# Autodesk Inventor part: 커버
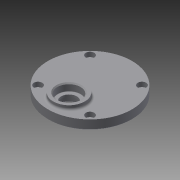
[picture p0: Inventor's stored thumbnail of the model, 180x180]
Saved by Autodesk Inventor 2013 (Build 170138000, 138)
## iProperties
Created: 2015-07
Part Number: 커버
Material: 일반
Document SubType Name: Modeling
Designer: user
Density: 1 g/cm^3
Author: user
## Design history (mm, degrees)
sketch "스케치1"
  geometry: C1 r 40 at (0, 0); 1 further point
  constraints: 1 centre point, 1 coincident
  dimensions: "d0" = 80 diameter of C1
extrude "돌출1" new body sketch "스케치1" distance "d1" = 9; taper "d2" = 0 deg
sketch "스케치2"
  geometry: C1 r 40 at (0, 0) reference; C2 r 15 at (0, -20)
  constraints: 1 centre point, 1 vertical alignment
  dimensions: "d3" = 30 diameter of C2; "d4" = 20 distance of C1.centre C2.centre
extrude "돌출2" join sketch "스케치2" distance "d5" = 4; taper "d6" = 0 deg
sketch "스케치3"
  geometry: C1 r 15 at (0, 0) reference; C2 r 11 at (0, 0); 1 further point
  constraints: 1 centre point, 1 coincident
  dimensions: "d7" = 22 diameter of C2
extrude "돌출3" cut sketch "스케치3" distance "d8" = 7; taper "d9" = 0 deg
sketch "스케치4"
  geometry: C1 r 11 at (0, 0) reference; C2 r 7.5 at (0, 0); 1 further point
  constraints: 1 centre point, 1 coincident
  dimensions: "d10" = 15 diameter of C2
extrude "돌출4" cut sketch "스케치4" distance "d12" = 2; taper "d13" = 0 deg
sketch "스케치5"
  geometry: C1 r 7.5 at (0, 0) reference; C2 r 11 at (0, 0); 1 further point
  constraints: 1 centre point, 1 coincident
  dimensions: "d14" = 22 diameter of C2
extrude "돌출5" cut sketch "스케치5" distance "d15" = 7; taper "d16" = 0 deg
sketch "스케치6"
  geometry: C1 r 11 at (0, -20) reference; C2 r 40 at (0, 0) reference; C3 r 14 at (0, -20); C4 r 14 at (0, 11)
  constraints: 2 centre point, 1 coincident, 1 vertical alignment
  dimensions: "d17" = 28 diameter of C3; "d18" = 28 diameter of C4; "d19" = 11 distance of C2.centre C4.centre
extrude "돌출6" join sketch "스케치6" distance "d20" = 3; taper "d21" = 0 deg
sketch "스케치7"
  geometry: C1 r 14 at (0, 0) reference; C2 r 11 at (0, 0); 1 further point
  constraints: 1 centre point, 1 coincident
  dimensions: "d22" = 22 diameter of C2
extrude "돌출7" cut sketch "스케치7" distance "d23" = 7; taper "d24" = 0 deg
sketch "스케치8"
  geometry: C1 r 9 at (0, 0); 2 further points
  constraints: 1 centre point, 1 coincident, 1 vertical alignment
  dimensions: "d25" = 18 diameter of C1
extrude "돌출8" cut sketch "스케치8" distance "d26" = 1; taper "d27" = 0 deg
sketch "스케치9"
  geometry: L1 (0, 0)-(16.369, 0); L2 (24.749, 24.749)-(-24.749, -24.749); L3 (-24.749, 24.749)-(24.749, -24.749); C1 r 40 at (0, 0) reference; C2 r 2.25 at (-24.749, 24.749); A1 r 35 centre (0, 0) between (24.749, 24.749) and (-24.749, -24.749)
  constraints: 6 end point, 4 point on circle, 2 centre point, 2 coincident, 2 midpoint, 1 horizontal
  dimensions: "d28" = 70 diameter of A1; "d29" = 45 deg angle of L1 L2; "d31" = 90 deg angle of L3 L2; "d33" = 4.5 diameter of C2
extrude "돌출9" cut sketch "스케치9" distance "d34" = 4.6; taper "d35" = 0 deg
sketch "스케치10"
  geometry: C1 r 2.25 at (0, 0) reference; C2 r 4 at (0, 0); 1 further point
  constraints: 1 centre point, 1 coincident
  dimensions: "d39" = 8 diameter of C2
extrude "돌출10" cut sketch "스케치10" distance "d40" = 4.4; taper "d41" = 0 deg
fillet "모깎기1" dims "d45" = 0.3
chamfer "모따기1" distance "d46" = 1; stored, may be unused: second distance "d47" = 2, angle "d48" = 45 deg
fillet "모깎기2" dims "d49" = 2
chamfer "모따기2" distance "d50" = 1; stored, may be unused: second distance "d51" = 2, angle "d52" = 45 deg
fillet "모깎기3" dims "d53" = 2
node "솔리드1"
pattern_circular "원형 패턴1" dims angle "d37" = 360 deg
pattern_circular "원형 패턴2" dims angle "d43" = 360 deg
